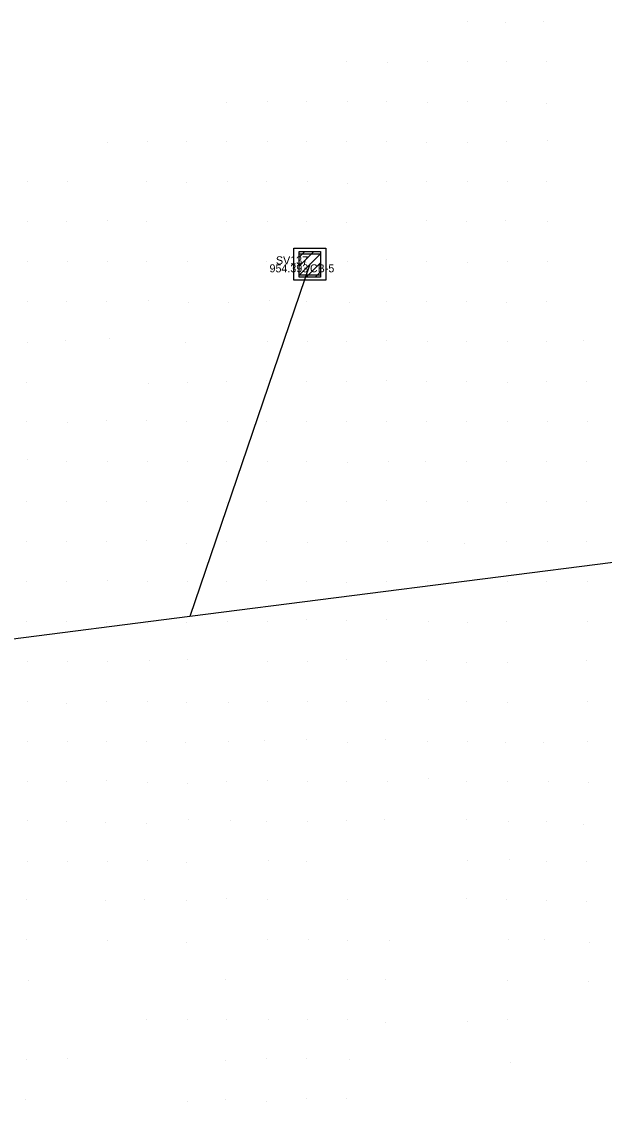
# Model space of a CAD drawing. Extents: x 2262025 to 2264532, y 740981 to 742724.
# Drawn here: x 2263155.6 to 2263228.5, y 742204.6 to 742339.5 of the extents above; entities that cross this region are included whole.
import ezdxf

# ---------------------------------------------------------------- set-up
doc = ezdxf.new("R2010")
doc.units = 0
for name, color, linetype in [('Ground Shots', 7, 'Continuous'), ('HY_X_Spring_Cells', 7, 'Continuous'), ('RW_X_CL', 7, 'Continuous'), ('RW_X_CL_100_Curve_Data', 7, 'Continuous'), ('RW_X_CL_100_Stations', 7, 'Continuous'), ('RW_X_CL_500_Stations', 7, 'Continuous'), ('SV_X_Text_Comment', 7, 'Continuous')]:
    doc.layers.add(name, color=color, linetype=linetype)

msp = doc.modelspace()

# ---------------------------------------------------------------- linework, layer by layer
at = {"layer": 'Ground Shots'}
for p, q in [((2263211.35, 742339.53), (2263211.35, 742339.53)), ((2263216.14, 742339.39), (2263216.14, 742339.39)), ((2263220.9, 742339.48), (2263220.9, 742339.48)), ((2263196.29, 742334.56), (2263196.29, 742334.56)), ((2263201.33, 742334.4), (2263201.33, 742334.4)), ((2263206.35, 742334.48), (2263206.35, 742334.48)), ((2263211.34, 742334.55), (2263211.34, 742334.55)), ((2263216.29, 742334.52), (2263216.29, 742334.52)), ((2263221.24, 742334.53), (2263221.24, 742334.53)), ((2263181.25, 742329.37), (2263181.25, 742329.37)), ((2263186.36, 742329.59), (2263186.36, 742329.59)), ((2263191.31, 742329.53), (2263191.31, 742329.53)), ((2263196.34, 742329.58), (2263196.34, 742329.58)), ((2263201.28, 742329.5), (2263201.28, 742329.5)), ((2263206.38, 742329.47), (2263206.38, 742329.47)), ((2263211.34, 742329.51), (2263211.34, 742329.51)), ((2263216.23, 742329.53), (2263216.23, 742329.53)), ((2263221.27, 742329.35), (2263221.27, 742329.35)), ((2263166.34, 742324.47), (2263166.34, 742324.47)), ((2263171.35, 742324.55), (2263171.35, 742324.55)), ((2263176.24, 742324.55), (2263176.24, 742324.55)), ((2263181.28, 742324.51), (2263181.28, 742324.51)), ((2263186.35, 742324.49), (2263186.35, 742324.49)), ((2263191.31, 742324.5), (2263191.31, 742324.5)), ((2263196.29, 742324.48), (2263196.29, 742324.48)), ((2263201.3, 742324.49), (2263201.3, 742324.49)), ((2263206.26, 742324.42), (2263206.26, 742324.42)), ((2263211.35, 742324.44), (2263211.35, 742324.44)), ((2263216.23, 742324.56), (2263216.23, 742324.56)), ((2263221.34, 742324.65), (2263221.34, 742324.65)), ((2263156.36, 742319.51), (2263156.36, 742319.51)), ((2263161.38, 742319.54), (2263161.38, 742319.54)), ((2263171.29, 742319.49), (2263171.29, 742319.49)), ((2263176.3, 742319.47), (2263176.3, 742319.47)), ((2263181.37, 742319.55), (2263181.37, 742319.55)), ((2263186.28, 742319.54), (2263186.28, 742319.54)), ((2263191.32, 742319.56), (2263191.32, 742319.56)), ((2263196.34, 742319.3), (2263196.34, 742319.3)), ((2263201.27, 742319.5), (2263201.27, 742319.5)), ((2263206.26, 742319.51), (2263206.26, 742319.51)), ((2263211.34, 742319.53), (2263211.34, 742319.53)), ((2263216.32, 742319.54), (2263216.32, 742319.54)), ((2263221.28, 742319.5), (2263221.28, 742319.5)), ((2263156.33, 742314.49), (2263156.33, 742314.49)), ((2263161.31, 742314.52), (2263161.31, 742314.52)), ((2263166.36, 742314.61), (2263166.36, 742314.61)), ((2263171.28, 742314.49), (2263171.28, 742314.49)), ((2263181.31, 742314.57), (2263181.31, 742314.57)), ((2263186.33, 742314.54), (2263186.33, 742314.54)), ((2263191.31, 742314.53), (2263191.31, 742314.53)), ((2263196.25, 742314.37), (2263196.25, 742314.37)), ((2263206.23, 742314.69), (2263206.23, 742314.69)), ((2263211.26, 742314.6), (2263211.26, 742314.6)), ((2263216.17, 742314.65), (2263216.17, 742314.65)), ((2263221.33, 742314.54), (2263221.33, 742314.54)), ((2263156.32, 742309.57), (2263156.32, 742309.57)), ((2263161.33, 742309.52), (2263161.33, 742309.52)), ((2263166.42, 742309.52), (2263166.42, 742309.52)), ((2263171.31, 742309.51), (2263171.31, 742309.51)), ((2263176.35, 742309.59), (2263176.35, 742309.59)), ((2263186.31, 742309.55), (2263186.31, 742309.55)), ((2263191.3, 742309.48), (2263191.3, 742309.48)), ((2263196.33, 742309.59), (2263196.33, 742309.59)), ((2263201.28, 742309.77), (2263201.28, 742309.77)), ((2263206.3, 742309.58), (2263206.3, 742309.58)), ((2263211.39, 742309.48), (2263211.39, 742309.48)), ((2263216.34, 742309.53), (2263216.34, 742309.53)), ((2263221.34, 742309.54), (2263221.34, 742309.54)), ((2263156.37, 742304.53), (2263156.37, 742304.53)), ((2263161.27, 742304.59), (2263161.27, 742304.59)), ((2263166.27, 742304.57), (2263166.27, 742304.57)), ((2263171.47, 742304.63), (2263171.47, 742304.63)), ((2263176.56, 742304.48), (2263176.56, 742304.48)), ((2263181.5, 742304.38), (2263181.5, 742304.38)), ((2263186.59, 742304.73), (2263186.59, 742304.73)), ((2263191.25, 742304.59), (2263191.25, 742304.59)), ((2263196.61, 742304.37), (2263196.61, 742304.37)), ((2263201.27, 742304.55), (2263201.27, 742304.55)), ((2263206.3, 742304.58), (2263206.3, 742304.58)), ((2263211.3, 742304.53), (2263211.3, 742304.53)), ((2263216.31, 742304.48), (2263216.31, 742304.48)), ((2263221.21, 742304.49), (2263221.21, 742304.49)), ((2263161.12, 742299.68), (2263161.12, 742299.68)), ((2263166.61, 742299.87), (2263166.61, 742299.87)), ((2263186.39, 742299.6), (2263186.39, 742299.6)), ((2263191.34, 742299.54), (2263191.34, 742299.54)), ((2263196.29, 742299.52), (2263196.29, 742299.52)), ((2263201.3, 742299.65), (2263201.3, 742299.65)), ((2263206.35, 742299.57), (2263206.35, 742299.57)), ((2263211.31, 742299.5), (2263211.31, 742299.5)), ((2263216.33, 742299.53), (2263216.33, 742299.53)), ((2263221.3, 742299.52), (2263221.3, 742299.52)), ((2263225.93, 742299.61), (2263225.93, 742299.61)), ((2263156.42, 742299.42), (2263156.42, 742299.42)), ((2263176.11, 742299.43), (2263176.11, 742299.43)), ((2263156.2, 742294.46), (2263156.2, 742294.46)), ((2263171.5, 742294.31), (2263171.5, 742294.31)), ((2263176.37, 742294.48), (2263176.37, 742294.48)), ((2263181.28, 742294.55), (2263181.28, 742294.55)), ((2263186.31, 742294.71), (2263186.31, 742294.71)), ((2263191.31, 742294.56), (2263191.31, 742294.56)), ((2263196.3, 742294.55), (2263196.3, 742294.55)), ((2263201.21, 742294.7), (2263201.21, 742294.7)), ((2263206.31, 742294.5), (2263206.31, 742294.5)), ((2263211.27, 742294.53), (2263211.27, 742294.53)), ((2263216.32, 742294.47), (2263216.32, 742294.47)), ((2263221.24, 742294.58), (2263221.24, 742294.58)), ((2263226.24, 742294.56), (2263226.24, 742294.56)), ((2263156.31, 742289.51), (2263156.31, 742289.51)), ((2263161.43, 742289.48), (2263161.43, 742289.48)), ((2263166.31, 742289.61), (2263166.31, 742289.61)), ((2263171.31, 742289.61), (2263171.31, 742289.61)), ((2263176.31, 742289.57), (2263176.31, 742289.57)), ((2263181.36, 742289.6), (2263181.36, 742289.6)), ((2263186.28, 742289.53), (2263186.28, 742289.53)), ((2263191.27, 742289.53), (2263191.27, 742289.53)), ((2263196.29, 742289.56), (2263196.29, 742289.56)), ((2263201.3, 742289.55), (2263201.3, 742289.55)), ((2263206.29, 742289.56), (2263206.29, 742289.56)), ((2263211.28, 742289.55), (2263211.28, 742289.55)), ((2263216.34, 742289.56), (2263216.34, 742289.56)), ((2263221.32, 742289.58), (2263221.32, 742289.58)), ((2263226.32, 742289.51), (2263226.32, 742289.51)), ((2263156.42, 742284.78), (2263156.42, 742284.78)), ((2263161.26, 742284.56), (2263161.26, 742284.56)), ((2263166.35, 742284.49), (2263166.35, 742284.49)), ((2263171.32, 742284.54), (2263171.32, 742284.54)), ((2263176.32, 742284.57), (2263176.32, 742284.57)), ((2263181.28, 742284.56), (2263181.28, 742284.56)), ((2263186.4, 742284.55), (2263186.4, 742284.55)), ((2263191.26, 742284.58), (2263191.26, 742284.58)), ((2263196.34, 742284.47), (2263196.34, 742284.47)), ((2263201.48, 742284.59), (2263201.48, 742284.59)), ((2263206.12, 742284.58), (2263206.12, 742284.58)), ((2263211.24, 742284.6), (2263211.24, 742284.6)), ((2263216.2, 742284.59), (2263216.2, 742284.59)), ((2263221.28, 742284.53), (2263221.28, 742284.53)), ((2263226.23, 742284.53), (2263226.23, 742284.53)), ((2263156.27, 742279.6), (2263156.27, 742279.6)), ((2263161.29, 742279.52), (2263161.29, 742279.52)), ((2263166.27, 742279.52), (2263166.27, 742279.52)), ((2263171.31, 742279.55), (2263171.31, 742279.55)), ((2263176.35, 742279.51), (2263176.35, 742279.51)), ((2263181.25, 742279.39), (2263181.25, 742279.39)), ((2263186.3, 742279.49), (2263186.3, 742279.49)), ((2263191.29, 742279.6), (2263191.29, 742279.6)), ((2263196.29, 742279.56), (2263196.29, 742279.56)), ((2263201.24, 742279.68), (2263201.24, 742279.68)), ((2263206.31, 742279.57), (2263206.31, 742279.57)), ((2263211.35, 742279.54), (2263211.35, 742279.54)), ((2263216.24, 742279.48), (2263216.24, 742279.48)), ((2263221.29, 742279.57), (2263221.29, 742279.57)), ((2263226.27, 742279.52), (2263226.27, 742279.52)), ((2263156.3, 742274.55), (2263156.3, 742274.55)), ((2263161.28, 742274.53), (2263161.28, 742274.53)), ((2263166.31, 742274.54), (2263166.31, 742274.54)), ((2263171.2, 742274.67), (2263171.2, 742274.67)), ((2263176.27, 742274.31), (2263176.27, 742274.31)), ((2263181.29, 742274.55), (2263181.29, 742274.55)), ((2263186.3, 742274.51), (2263186.3, 742274.51)), ((2263191.34, 742274.48), (2263191.34, 742274.48)), ((2263196.3, 742274.51), (2263196.3, 742274.51)), ((2263201.34, 742274.49), (2263201.34, 742274.49)), ((2263206.35, 742274.57), (2263206.35, 742274.57)), ((2263211.06, 742274.3), (2263211.06, 742274.3)), ((2263216.27, 742274.56), (2263216.27, 742274.56)), ((2263221.33, 742274.5), (2263221.33, 742274.5)), ((2263226.26, 742274.55), (2263226.26, 742274.55)), ((2263156.28, 742269.57), (2263156.28, 742269.57)), ((2263161.3, 742269.53), (2263161.3, 742269.53)), ((2263166.32, 742269.65), (2263166.32, 742269.65)), ((2263171.33, 742269.53), (2263171.33, 742269.53)), ((2263176.32, 742269.58), (2263176.32, 742269.58)), ((2263181.26, 742269.55), (2263181.26, 742269.55)), ((2263186.19, 742269.67), (2263186.19, 742269.67)), ((2263191.28, 742269.51), (2263191.28, 742269.51)), ((2263196.28, 742269.48), (2263196.28, 742269.48)), ((2263201.31, 742269.51), (2263201.31, 742269.51)), ((2263206.36, 742269.55), (2263206.36, 742269.55)), ((2263211.26, 742269.53), (2263211.26, 742269.53)), ((2263216.34, 742269.51), (2263216.34, 742269.51)), ((2263221.27, 742269.53), (2263221.27, 742269.53)), ((2263226.33, 742269.55), (2263226.33, 742269.55)), ((2263156.25, 742264.55), (2263156.25, 742264.55)), ((2263161.31, 742264.53), (2263161.31, 742264.53)), ((2263166.29, 742264.47), (2263166.29, 742264.47)), ((2263176.31, 742264.42), (2263176.31, 742264.42)), ((2263181.33, 742264.59), (2263181.33, 742264.59)), ((2263186.36, 742264.5), (2263186.36, 742264.5)), ((2263191.31, 742264.8), (2263191.31, 742264.8)), ((2263196.24, 742264.68), (2263196.24, 742264.68)), ((2263201.21, 742264.74), (2263201.21, 742264.74)), ((2263206.52, 742264.57), (2263206.52, 742264.57)), ((2263211.4, 742264.47), (2263211.4, 742264.47)), ((2263216.2, 742264.52), (2263216.2, 742264.52)), ((2263226.32, 742264.56), (2263226.32, 742264.56)), ((2263171.34, 742264.36), (2263171.34, 742264.36)), ((2263156.36, 742259.61), (2263156.36, 742259.61)), ((2263161.33, 742259.55), (2263161.33, 742259.55)), ((2263166.32, 742259.51), (2263166.32, 742259.51)), ((2263171.59, 742259.63), (2263171.59, 742259.63)), ((2263176.38, 742259.78), (2263176.38, 742259.78)), ((2263186.39, 742259.61), (2263186.39, 742259.61)), ((2263191.34, 742259.54), (2263191.34, 742259.54)), ((2263196.21, 742259.78), (2263196.21, 742259.78)), ((2263201.29, 742259.52), (2263201.29, 742259.52)), ((2263206.26, 742259.63), (2263206.26, 742259.63)), ((2263211.3, 742259.42), (2263211.3, 742259.42)), ((2263216.32, 742259.47), (2263216.32, 742259.47)), ((2263226.3, 742259.62), (2263226.3, 742259.62)), ((2263156.32, 742254.54), (2263156.32, 742254.54)), ((2263161.22, 742254.35), (2263161.22, 742254.35)), ((2263166.28, 742254.56), (2263166.28, 742254.56)), ((2263171.32, 742254.6), (2263171.32, 742254.6)), ((2263176.24, 742254.44), (2263176.24, 742254.44)), ((2263181.51, 742254.41), (2263181.51, 742254.41)), ((2263186.32, 742254.56), (2263186.32, 742254.56)), ((2263191.32, 742254.6), (2263191.32, 742254.6)), ((2263196.28, 742254.58), (2263196.28, 742254.58)), ((2263201.28, 742254.59), (2263201.28, 742254.59)), ((2263206.47, 742254.78), (2263206.47, 742254.78)), ((2263211.24, 742254.53), (2263211.24, 742254.53)), ((2263216.43, 742254.47), (2263216.43, 742254.47)), ((2263226.35, 742254.49), (2263226.35, 742254.49)), ((2263156.36, 742249.6), (2263156.36, 742249.6)), ((2263161.35, 742249.59), (2263161.35, 742249.59)), ((2263166.31, 742249.55), (2263166.31, 742249.55)), ((2263171.28, 742249.56), (2263171.28, 742249.56)), ((2263181.44, 742249.58), (2263181.44, 742249.58)), ((2263186.05, 742249.62), (2263186.05, 742249.62)), ((2263191.26, 742249.74), (2263191.26, 742249.74)), ((2263201.13, 742249.76), (2263201.13, 742249.76)), ((2263211.43, 742249.56), (2263211.43, 742249.56)), ((2263176.15, 742249.47), (2263176.15, 742249.47)), ((2263196.42, 742249.48), (2263196.42, 742249.48)), ((2263206.37, 742249.53), (2263206.37, 742249.53)), ((2263216.16, 742249.48), (2263216.16, 742249.48)), ((2263220.92, 742249.48), (2263220.92, 742249.48)), ((2263226.37, 742249.54), (2263226.37, 742249.54)), ((2263156.37, 742244.6), (2263156.37, 742244.6)), ((2263161.23, 742244.6), (2263161.23, 742244.6)), ((2263166.24, 742244.62), (2263166.24, 742244.62)), ((2263171.32, 742244.43), (2263171.32, 742244.43)), ((2263176.36, 742244.34), (2263176.36, 742244.34)), ((2263181.29, 742244.52), (2263181.29, 742244.52)), ((2263186.35, 742244.73), (2263186.35, 742244.73)), ((2263191.33, 742244.51), (2263191.33, 742244.51)), ((2263196.25, 742244.55), (2263196.25, 742244.55)), ((2263201.33, 742244.55), (2263201.33, 742244.55)), ((2263206.5, 742244.93), (2263206.5, 742244.93)), ((2263211.29, 742244.54), (2263211.29, 742244.54)), ((2263216.33, 742244.58), (2263216.33, 742244.58)), ((2263221.51, 742244.55), (2263221.51, 742244.55)), ((2263226.44, 742244.46), (2263226.44, 742244.46)), ((2263156.39, 742239.68), (2263156.39, 742239.68)), ((2263161.25, 742239.54), (2263161.25, 742239.54)), ((2263166.11, 742239.42), (2263166.11, 742239.42)), ((2263171.22, 742239.35), (2263171.22, 742239.35)), ((2263176.45, 742239.76), (2263176.45, 742239.76)), ((2263181.69, 742239.73), (2263181.69, 742239.73)), ((2263186.3, 742239.52), (2263186.3, 742239.52)), ((2263191.36, 742239.58), (2263191.36, 742239.58)), ((2263196.26, 742239.63), (2263196.26, 742239.63)), ((2263201.06, 742239.8), (2263201.06, 742239.8)), ((2263211.2, 742239.78), (2263211.2, 742239.78)), ((2263216.51, 742239.59), (2263216.51, 742239.59)), ((2263221.28, 742239.56), (2263221.28, 742239.56)), ((2263225.82, 742239.16), (2263225.82, 742239.16)), ((2263171.34, 742234.71), (2263171.34, 742234.71)), ((2263216.61, 742234.8), (2263216.61, 742234.8)), ((2263156.33, 742234.53), (2263156.33, 742234.53)), ((2263161.33, 742234.59), (2263161.33, 742234.59)), ((2263166.34, 742234.56), (2263166.34, 742234.56)), ((2263176.26, 742234.47), (2263176.26, 742234.47)), ((2263186.52, 742234.66), (2263186.52, 742234.66)), ((2263191.2, 742234.6), (2263191.2, 742234.6)), ((2263211.37, 742234.65), (2263211.37, 742234.65)), ((2263221.22, 742234.51), (2263221.22, 742234.51)), ((2263226.28, 742234.58), (2263226.28, 742234.58)), ((2263156.31, 742229.75), (2263156.31, 742229.75)), ((2263166.14, 742229.7), (2263166.14, 742229.7)), ((2263170.99, 742229.81), (2263170.99, 742229.81)), ((2263176.19, 742229.68), (2263176.19, 742229.68)), ((2263181.19, 742229.88), (2263181.19, 742229.88)), ((2263186.34, 742229.77), (2263186.34, 742229.77)), ((2263196.4, 742229.78), (2263196.4, 742229.78)), ((2263211.3, 742229.93), (2263211.3, 742229.93)), ((2263216.19, 742229.76), (2263216.19, 742229.76)), ((2263221.29, 742229.73), (2263221.29, 742229.73)), ((2263226.29, 742229.56), (2263226.29, 742229.56)), ((2263156.29, 742224.76), (2263156.29, 742224.76)), ((2263166.43, 742224.73), (2263166.43, 742224.73)), ((2263176.2, 742224.4), (2263176.2, 742224.4)), ((2263186.34, 742224.82), (2263186.34, 742224.82)), ((2263191.5, 742224.77), (2263191.5, 742224.77)), ((2263196.33, 742224.73), (2263196.33, 742224.73)), ((2263201.6, 742224.63), (2263201.6, 742224.63)), ((2263216.55, 742224.8), (2263216.55, 742224.8)), ((2263221.04, 742224.75), (2263221.04, 742224.75)), ((2263226.57, 742224.41), (2263226.57, 742224.41)), ((2263156.44, 742219.66), (2263156.44, 742219.66)), ((2263181.09, 742219.84), (2263181.09, 742219.84)), ((2263196.37, 742219.82), (2263196.37, 742219.82)), ((2263201.12, 742219.78), (2263201.12, 742219.78)), ((2263216.41, 742219.65), (2263216.41, 742219.65)), ((2263226.48, 742219.51), (2263226.48, 742219.51)), ((2263171.22, 742214.82), (2263171.22, 742214.82)), ((2263176.39, 742214.77), (2263176.39, 742214.77)), ((2263181.29, 742214.82), (2263181.29, 742214.82)), ((2263186.44, 742214.8), (2263186.44, 742214.8)), ((2263191.38, 742214.77), (2263191.38, 742214.77)), ((2263196.35, 742214.79), (2263196.35, 742214.79)), ((2263211.39, 742214.59), (2263211.39, 742214.59)), ((2263216.38, 742214.82), (2263216.38, 742214.82)), ((2263201.11, 742214.4), (2263201.11, 742214.4)), ((2263156.21, 742209.86), (2263156.21, 742209.86)), ((2263161.33, 742209.94), (2263161.33, 742209.94)), ((2263181.15, 742209.67), (2263181.15, 742209.67)), ((2263186.26, 742209.93), (2263186.26, 742209.93)), ((2263191.27, 742209.94), (2263191.27, 742209.94)), ((2263196.59, 742209.78), (2263196.59, 742209.78)), ((2263216.72, 742209.47), (2263216.72, 742209.47)), ((2263156.18, 742204.82), (2263156.18, 742204.82)), ((2263176.33, 742204.57), (2263176.33, 742204.57)), ((2263181.15, 742204.8), (2263181.15, 742204.8)), ((2263186.2, 742204.57), (2263186.2, 742204.57)), ((2263191.28, 742204.89), (2263191.28, 742204.89)), ((2263196.2, 742204.94), (2263196.2, 742204.94))]:
    msp.add_line(p, q, dxfattribs=at)
at = {"layer": 'RW_X_CL_100_Curve_Data'}
for p, q in [((2263190.35, 742308.97), (2263192.18, 742310.8)), ((2263190.35, 742310.1), (2263191.05, 742310.8)), ((2263190.35, 742308.97), (2263192.18, 742310.8)), ((2263190.35, 742310.1), (2263191.05, 742310.8)), ((2263190.35, 742307.83), (2263193.01, 742310.5)), ((2263190.35, 742307.83), (2263193.01, 742310.5)), ((2263191.22, 742307.57), (2263193.01, 742309.37)), ((2263191.22, 742307.57), (2263193.01, 742309.37)), ((2263192.35, 742307.57), (2263193.01, 742308.24)), ((2263192.35, 742307.57), (2263193.01, 742308.24))]:
    msp.add_line(p, q, dxfattribs=at)
for points in [[(2263189.68, 742311.19), (2263193.68, 742311.19), (2263193.68, 742307.19), (2263189.68, 742307.19)], [(2263189.68, 742311.19), (2263193.68, 742311.19), (2263193.68, 742307.19), (2263189.68, 742307.19)], [(2263190.35, 742310.8), (2263193.01, 742310.8), (2263193.01, 742307.57), (2263190.35, 742307.57)], [(2263190.35, 742310.8), (2263193.01, 742310.8), (2263193.01, 742307.57), (2263190.35, 742307.57)], [(2263190.35, 742310.52), (2263193.01, 742310.52), (2263193.01, 742307.85), (2263190.35, 742307.85)], [(2263190.35, 742310.52), (2263193.01, 742310.52), (2263193.01, 742307.85), (2263190.35, 742307.85)]]:
    msp.add_lwpolyline(points, close=True, dxfattribs=at)
at = {"layer": 'RW_X_CL_100_Stations'}
for p, q in [((2263191.68, 742311.19), (2263191.68, 742311.19)), ((2263191.68, 742311.19), (2263191.68, 742311.19)), ((2263191.68, 742310.52), (2263191.68, 742310.52)), ((2263191.68, 742310.52), (2263191.68, 742310.52)), ((2263190.35, 742309.19), (2263190.35, 742309.19)), ((2263190.35, 742309.19), (2263190.35, 742309.19)), ((2263191.68, 742309.19), (2263191.68, 742309.19)), ((2263191.68, 742309.19), (2263191.68, 742309.19)), ((2263191.68, 742309.19), (2263191.68, 742309.19)), ((2263191.68, 742309.19), (2263191.68, 742309.19)), ((2263193.01, 742309.19), (2263193.01, 742309.19)), ((2263193.01, 742309.19), (2263193.01, 742309.19)), ((2263191.68, 742307.85), (2263191.68, 742307.85)), ((2263191.68, 742307.85), (2263191.68, 742307.85)), ((2263191.68, 742307.57), (2263191.68, 742307.57)), ((2263191.68, 742307.57), (2263191.68, 742307.57)), ((2263191.68, 742307.19), (2263191.68, 742307.19)), ((2263191.68, 742307.19), (2263191.68, 742307.19))]:
    msp.add_line(p, q, dxfattribs=at)
at = {"layer": 'RW_X_CL_500_Stations'}
for p, q in [((2263191.68, 742309.19), (2263176.67, 742265.17)), ((2263398.72, 742293.58), (2263176.67, 742265.17)), ((2263176.67, 742265.17), (2263092.14, 742254.36))]:
    msp.add_line(p, q, dxfattribs=at)

# ---------------------------------------------------------------- texts
at = {"layer": 'HY_X_Spring_Cells'}
msp.add_text('954.393', height=1, dxfattribs=at).set_placement((2263186.63, 742308.19))
msp.add_text('954.393', height=1, dxfattribs=at).set_placement((2263186.63, 742308.19))
at = {"layer": 'RW_X_CL'}
msp.add_text('CB-5', height=1, dxfattribs=at).set_placement((2263191.68, 742308.19))
msp.add_text('CB-5', height=1, dxfattribs=at).set_placement((2263191.68, 742308.19))
at = {"layer": 'SV_X_Text_Comment'}
msp.add_text('SV137', height=1, dxfattribs=at).set_placement((2263187.43, 742309.19))
msp.add_text('SV137', height=1, dxfattribs=at).set_placement((2263187.43, 742309.19))

doc.saveas('drawing.dxf')
